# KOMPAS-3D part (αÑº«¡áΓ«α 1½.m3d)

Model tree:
1. Эскиз:1
2. Операция выдавливания:36
     Толщина стенки 1 = 2; Толщина стенки 2 = 6; Расстояние 1 = 1; Расстояние 2 = 3
3. Эскиз:38
4. Операция выдавливания:40
     Толщина стенки 1 = 2; Толщина стенки 2 = 6; Расстояние 1 = 5; Расстояние 2 = 3
5. Эскиз:39
6. Операция выдавливания:41
     Толщина стенки 1 = 2; Толщина стенки 2 = 6; Расстояние 1 = 1; Расстояние 2 = 3
7. Эскиз:40
8. Операция выдавливания:42
     Толщина стенки 1 = 2; Толщина стенки 2 = 2.5; Расстояние 1 = 50; Расстояние 2 = 3
9. Эскиз:41
10. Вырезать элемент выдавливания:4
     Толщина стенки 2 = 1.5; Расстояние 1 = 40
11. Эскиз:42
12. Операция выдавливания:43
     Толщина стенки 1 = 2; Толщина стенки 2 = 2.5; Расстояние 1 = 50; Расстояние 2 = 3
13. Эскиз:43
14. Вырезать элемент выдавливания:5
     Толщина стенки 2 = 1.5; Расстояние 1 = 40
15. Эскиз:44
16. Операция выдавливания:44
     Толщина стенки 1 = 2; Толщина стенки 2 = 2.5; Расстояние 1 = 10; Расстояние 2 = 3
17. Эскиз:45
18. Эскиз:46
19. Операция выдавливания:47
     Толщина стенки 1 = 2; Толщина стенки 2 = 6; Расстояние 1 = 1; Расстояние 2 = 3
20. Эскиз:47
21. Операция выдавливания:48
     Толщина стенки 1 = 2; Толщина стенки 2 = 6; Расстояние 1 = 5; Расстояние 2 = 3
22. Эскиз:48
23. Операция выдавливания:49
     Толщина стенки 1 = 2; Толщина стенки 2 = 6; Расстояние 1 = 1; Расстояние 2 = 3
24. Эскиз:49
25. Вырезать элемент выдавливания:6
     Толщина стенки 2 = 1.5; Расстояние 1 = 22
26. Эскиз:50
27. Вырезать элемент выдавливания:7
     Толщина стенки 2 = 1.5; Расстояние 1 = 1
28. Эскиз:51
29. Вырезать элемент выдавливания:8
     Толщина стенки 2 = 1.5; Расстояние 1 = 151
30. Эскиз:53
31. Операция выдавливания:50
     Толщина стенки 1 = 2; Толщина стенки 2 = 6; Расстояние 1 = 1; Расстояние 2 = 0.5
